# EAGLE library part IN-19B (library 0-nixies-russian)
IN-19B: medium symbol frontview nixie tube
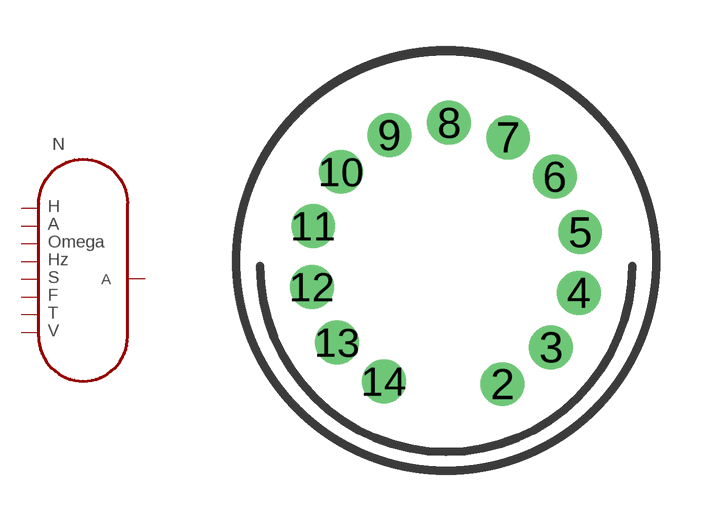
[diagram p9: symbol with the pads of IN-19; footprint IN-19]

Designator prefix N

## IN-19B  [IN-19]
2  P$5
4  P$6
5  P$1
6  P$8
8  A
10  P$7
11  P$2
12  P$3
14  P$4

## Footprint IN-19 (pad centres in mm)
drill 0.84 round: 2 1.733,-3.786; 3 3.222,-2.652; 4 4.072,-0.985; 5 4.114,0.886; 6 3.34,2.59; 7 1.903,3.79; 8 0.089,4.247; 9 -1.745,3.872; 10 -3.234,2.738; 11 -4.084,1.07; 12 -4.126,-0.801; 13 -3.352,-2.505; 14 -1.915,-3.704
